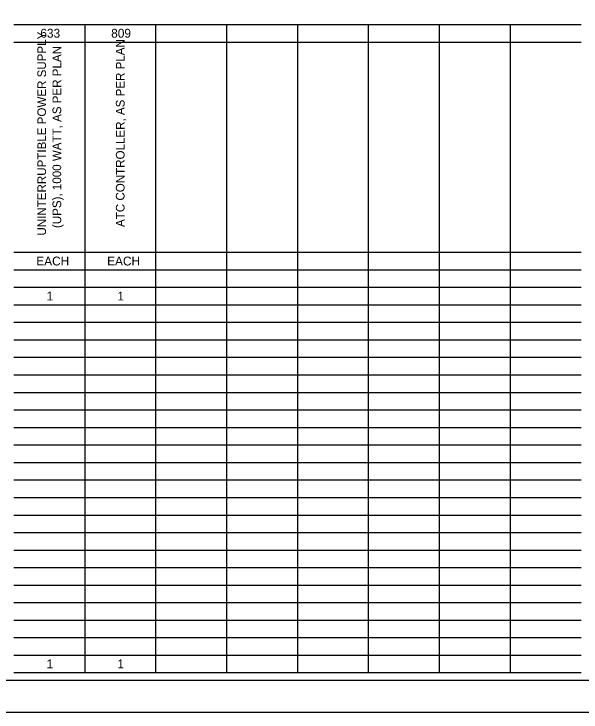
# Model space of a CAD drawing. Extents: x 0 to 34, y 0 to 22.
# Drawn here: x 16.33 to 25.28, y 0 to 11.03 of the extents above; entities that cross this region are included whole.
import ezdxf

# ---------------------------------------------------------------- set-up
doc = ezdxf.new("R2010")
doc.units = 0
for name, color, linetype in [('SH_Border', 7, 'Continuous'), ('SH_Cut_Line', 7, 'Continuous'), ('SH_Data', 7, 'Continuous')]:
    doc.layers.add(name, color=color, linetype=linetype)

msp = doc.modelspace()

# ---------------------------------------------------------------- linework, layer by layer
at = {"layer": 'SH_Border'}
msp.add_lwpolyline([(1.5, 21.5), (33.5, 21.5), (33.5, 0.5), (1.5, 0.5)], close=True, dxfattribs=at)
at = {"layer": 'SH_Cut_Line'}
msp.add_lwpolyline([(0, 0), (34, 0), (34, 22), (0, 22)], close=True, dxfattribs=at)
at = {"layer": 'SH_Data'}
for p, q in [((16.324, 10.86), (23.042, 10.86)), ((17.443, 10.86), (17.443, 10.583)), ((18.563, 10.86), (18.563, 10.583)), ((19.683, 10.86), (19.683, 10.583)), ((20.803, 10.86), (20.803, 10.583)), ((21.922, 10.86), (21.922, 10.583)), ((23.042, 10.86), (24.162, 10.86)), ((23.042, 10.86), (23.042, 10.583)), ((24.162, 10.86), (25.282, 10.86)), ((24.162, 10.86), (24.162, 10.583)), ((16.324, 10.583), (23.042, 10.583)), ((17.443, 10.583), (17.443, 10.307)), ((18.563, 10.583), (18.563, 10.307)), ((19.683, 10.583), (19.683, 10.307)), ((20.803, 10.583), (20.803, 10.307)), ((21.922, 10.583), (21.922, 10.307)), ((23.042, 10.583), (24.162, 10.583)), ((23.042, 10.583), (23.042, 10.307)), ((24.162, 10.583), (25.282, 10.583)), ((24.162, 10.583), (24.162, 10.307)), ((17.443, 10.307), (17.443, 10.03)), ((18.563, 10.307), (18.563, 10.03)), ((19.683, 10.307), (19.683, 10.03)), ((20.803, 10.307), (20.803, 10.03)), ((21.922, 10.307), (21.922, 10.03)), ((23.042, 10.307), (23.042, 10.03)), ((24.162, 10.307), (24.162, 10.03)), ((17.443, 10.03), (17.443, 9.753)), ((18.563, 10.03), (18.563, 9.753)), ((19.683, 10.03), (19.683, 9.753)), ((20.803, 10.03), (20.803, 9.753)), ((21.922, 10.03), (21.922, 9.753)), ((23.042, 10.03), (23.042, 9.753)), ((24.162, 10.03), (24.162, 9.753)), ((17.443, 9.753), (17.443, 9.476)), ((18.563, 9.753), (18.563, 9.476)), ((19.683, 9.753), (19.683, 9.476)), ((20.803, 9.753), (20.803, 9.476)), ((21.922, 9.753), (21.922, 9.476)), ((23.042, 9.753), (23.042, 9.476)), ((24.162, 9.753), (24.162, 9.476)), ((17.443, 9.476), (17.443, 9.2)), ((18.563, 9.476), (18.563, 9.2)), ((19.683, 9.476), (19.683, 9.2)), ((20.803, 9.476), (20.803, 9.2)), ((21.922, 9.476), (21.922, 9.2)), ((23.042, 9.476), (23.042, 9.2)), ((24.162, 9.476), (24.162, 9.2)), ((17.443, 9.2), (17.443, 8.923)), ((18.563, 9.2), (18.563, 8.923)), ((19.683, 9.2), (19.683, 8.923)), ((20.803, 9.2), (20.803, 8.923)), ((21.922, 9.2), (21.922, 8.923)), ((23.042, 9.2), (23.042, 8.923)), ((24.162, 9.2), (24.162, 8.923)), ((17.443, 8.923), (17.443, 8.646)), ((18.563, 8.923), (18.563, 8.646)), ((19.683, 8.923), (19.683, 8.646)), ((20.803, 8.923), (20.803, 8.646)), ((21.922, 8.923), (21.922, 8.646)), ((23.042, 8.923), (23.042, 8.646)), ((24.162, 8.923), (24.162, 8.646)), ((17.443, 8.646), (17.443, 8.37)), ((18.563, 8.646), (18.563, 8.37)), ((19.683, 8.646), (19.683, 8.37)), ((20.803, 8.646), (20.803, 8.37)), ((21.922, 8.646), (21.922, 8.37)), ((23.042, 8.646), (23.042, 8.37)), ((24.162, 8.646), (24.162, 8.37)), ((17.443, 8.37), (17.443, 8.093)), ((18.563, 8.37), (18.563, 8.093)), ((19.683, 8.37), (19.683, 8.093)), ((20.803, 8.37), (20.803, 8.093)), ((21.922, 8.37), (21.922, 8.093)), ((23.042, 8.37), (23.042, 8.093)), ((24.162, 8.37), (24.162, 8.093)), ((17.443, 8.093), (17.443, 7.816)), ((18.563, 8.093), (18.563, 7.816)), ((19.683, 8.093), (19.683, 7.816)), ((20.803, 8.093), (20.803, 7.816)), ((21.922, 8.093), (21.922, 7.816)), ((23.042, 8.093), (23.042, 7.816)), ((24.162, 8.093), (24.162, 7.816)), ((17.443, 7.816), (17.443, 7.54)), ((18.563, 7.816), (18.563, 7.54)), ((19.683, 7.816), (19.683, 7.54)), ((20.803, 7.816), (20.803, 7.54)), ((21.922, 7.816), (21.922, 7.54)), ((23.042, 7.816), (23.042, 7.54)), ((24.162, 7.816), (24.162, 7.54)), ((17.443, 7.54), (17.443, 7.263)), ((18.563, 7.54), (18.563, 7.263)), ((19.683, 7.54), (19.683, 7.263)), ((20.803, 7.54), (20.803, 7.263)), ((21.922, 7.54), (21.922, 7.263)), ((23.042, 7.54), (23.042, 7.263)), ((24.162, 7.54), (24.162, 7.263)), ((16.324, 7.263), (23.042, 7.263)), ((17.443, 7.263), (17.443, 6.986)), ((18.563, 7.263), (18.563, 6.986)), ((19.683, 7.263), (19.683, 6.986)), ((20.803, 7.263), (20.803, 6.986)), ((21.922, 7.263), (21.922, 6.986)), ((23.042, 7.263), (24.162, 7.263)), ((23.042, 7.263), (23.042, 6.986)), ((24.162, 7.263), (25.282, 7.263)), ((24.162, 7.263), (24.162, 6.986)), ((16.324, 6.986), (23.042, 6.986)), ((17.443, 6.986), (17.443, 6.709)), ((18.563, 6.986), (18.563, 6.709)), ((19.683, 6.986), (19.683, 6.709)), ((20.803, 6.986), (20.803, 6.709)), ((21.922, 6.986), (21.922, 6.709)), ((23.042, 6.986), (24.162, 6.986)), ((23.042, 6.986), (23.042, 6.709)), ((24.162, 6.986), (25.282, 6.986)), ((24.162, 6.986), (24.162, 6.709)), ((16.324, 6.709), (23.042, 6.709)), ((17.443, 6.709), (17.443, 6.433)), ((18.563, 6.709), (18.563, 6.433)), ((19.683, 6.709), (19.683, 6.433)), ((20.803, 6.709), (20.803, 6.433)), ((21.922, 6.709), (21.922, 6.433)), ((23.042, 6.709), (24.162, 6.709)), ((23.042, 6.709), (23.042, 6.433)), ((24.162, 6.709), (25.282, 6.709)), ((24.162, 6.709), (24.162, 6.433)), ((16.324, 6.433), (23.042, 6.433)), ((17.443, 6.433), (17.443, 5.879)), ((18.563, 6.433), (18.563, 5.879)), ((19.683, 6.433), (19.683, 5.879)), ((20.803, 6.433), (20.803, 5.879)), ((21.922, 6.433), (21.922, 5.879)), ((23.042, 6.433), (24.162, 6.433)), ((23.042, 6.433), (23.042, 5.879)), ((24.162, 6.433), (25.282, 6.433)), ((24.162, 6.433), (24.162, 5.879)), ((16.324, 6.156), (23.042, 6.156)), ((23.042, 6.156), (24.162, 6.156)), ((24.162, 6.156), (25.282, 6.156)), ((16.324, 5.879), (23.042, 5.879)), ((17.443, 5.879), (17.443, 5.603)), ((18.563, 5.879), (18.563, 5.603)), ((19.683, 5.879), (19.683, 5.603)), ((20.803, 5.879), (20.803, 5.603)), ((21.922, 5.879), (21.922, 5.603)), ((23.042, 5.879), (24.162, 5.879)), ((23.042, 5.879), (23.042, 5.603)), ((24.162, 5.879), (25.282, 5.879)), ((24.162, 5.879), (24.162, 5.603)), ((16.324, 5.603), (23.042, 5.603)), ((17.443, 5.603), (17.443, 5.326)), ((18.563, 5.603), (18.563, 5.326)), ((19.683, 5.603), (19.683, 5.326)), ((20.803, 5.603), (20.803, 5.326)), ((21.922, 5.603), (21.922, 5.326)), ((23.042, 5.603), (24.162, 5.603)), ((23.042, 5.603), (23.042, 5.326)), ((24.162, 5.603), (25.282, 5.603)), ((24.162, 5.603), (24.162, 5.326)), ((16.324, 5.326), (23.042, 5.326)), ((17.443, 5.326), (17.443, 5.049)), ((18.563, 5.326), (18.563, 5.049)), ((19.683, 5.326), (19.683, 5.049)), ((20.803, 5.326), (20.803, 5.049)), ((21.922, 5.326), (21.922, 5.049)), ((23.042, 5.326), (24.162, 5.326)), ((23.042, 5.326), (23.042, 5.049)), ((24.162, 5.326), (25.282, 5.326)), ((24.162, 5.326), (24.162, 5.049)), ((16.324, 5.049), (23.042, 5.049)), ((17.443, 5.049), (17.443, 4.496)), ((18.563, 5.049), (18.563, 4.496)), ((19.683, 5.049), (19.683, 4.496)), ((20.803, 5.049), (20.803, 4.496)), ((21.922, 5.049), (21.922, 4.496)), ((23.042, 5.049), (24.162, 5.049)), ((23.042, 5.049), (23.042, 4.496)), ((24.162, 5.049), (25.282, 5.049)), ((24.162, 5.049), (24.162, 4.496)), ((16.324, 4.772), (23.042, 4.772)), ((23.042, 4.772), (24.162, 4.772)), ((24.162, 4.772), (25.282, 4.772)), ((16.324, 4.496), (23.042, 4.496)), ((17.443, 4.496), (17.443, 4.219)), ((18.563, 4.496), (18.563, 4.219)), ((19.683, 4.496), (19.683, 4.219)), ((20.803, 4.496), (20.803, 4.219)), ((21.922, 4.496), (21.922, 4.219)), ((23.042, 4.496), (24.162, 4.496)), ((23.042, 4.496), (23.042, 4.219)), ((24.162, 4.496), (25.282, 4.496)), ((24.162, 4.496), (24.162, 4.219)), ((16.324, 4.219), (23.042, 4.219)), ((17.443, 4.219), (17.443, 3.942)), ((18.563, 4.219), (18.563, 3.942)), ((19.683, 4.219), (19.683, 3.942)), ((20.803, 4.219), (20.803, 3.942)), ((21.922, 4.219), (21.922, 3.942)), ((23.042, 4.219), (24.162, 4.219)), ((23.042, 4.219), (23.042, 3.942)), ((24.162, 4.219), (25.282, 4.219)), ((24.162, 4.219), (24.162, 3.942)), ((16.324, 3.942), (23.042, 3.942)), ((17.443, 3.942), (17.443, 3.666)), ((18.563, 3.942), (18.563, 3.666)), ((19.683, 3.942), (19.683, 3.666)), ((20.803, 3.942), (20.803, 3.666)), ((21.922, 3.942), (21.922, 3.666)), ((23.042, 3.942), (24.162, 3.942)), ((23.042, 3.942), (23.042, 3.666)), ((24.162, 3.942), (25.282, 3.942)), ((24.162, 3.942), (24.162, 3.666)), ((16.324, 3.666), (23.042, 3.666)), ((17.443, 3.666), (17.443, 3.112)), ((18.563, 3.666), (18.563, 3.112)), ((19.683, 3.666), (19.683, 3.112)), ((20.803, 3.666), (20.803, 3.112)), ((21.922, 3.666), (21.922, 3.112)), ((23.042, 3.666), (24.162, 3.666)), ((23.042, 3.666), (23.042, 3.112)), ((24.162, 3.666), (25.282, 3.666)), ((24.162, 3.666), (24.162, 3.112)), ((16.324, 3.389), (23.042, 3.389)), ((23.042, 3.389), (24.162, 3.389)), ((24.162, 3.389), (25.282, 3.389)), ((16.324, 3.112), (23.042, 3.112)), ((17.443, 3.112), (17.443, 2.836)), ((18.563, 3.112), (18.563, 2.836)), ((19.683, 3.112), (19.683, 2.836)), ((20.803, 3.112), (20.803, 2.836)), ((21.922, 3.112), (21.922, 2.836)), ((23.042, 3.112), (24.162, 3.112)), ((23.042, 3.112), (23.042, 2.836)), ((24.162, 3.112), (25.282, 3.112)), ((24.162, 3.112), (24.162, 2.836)), ((16.324, 2.836), (23.042, 2.836)), ((17.443, 2.836), (17.443, 2.005)), ((18.563, 2.836), (18.563, 2.005)), ((19.683, 2.836), (19.683, 2.005)), ((20.803, 2.836), (20.803, 2.005)), ((21.922, 2.836), (21.922, 2.005)), ((23.042, 2.836), (24.162, 2.836)), ((23.042, 2.836), (23.042, 2.005)), ((24.162, 2.836), (25.282, 2.836)), ((24.162, 2.836), (24.162, 2.005)), ((16.324, 2.559), (23.042, 2.559)), ((23.042, 2.559), (24.162, 2.559)), ((24.162, 2.559), (25.282, 2.559)), ((16.324, 2.282), (23.042, 2.282)), ((23.042, 2.282), (24.162, 2.282)), ((24.162, 2.282), (25.282, 2.282)), ((16.324, 2.005), (23.042, 2.005)), ((17.443, 2.005), (17.443, 1.729)), ((18.563, 2.005), (18.563, 1.729)), ((19.683, 2.005), (19.683, 1.729)), ((20.803, 2.005), (20.803, 1.729)), ((21.922, 2.005), (21.922, 1.729)), ((23.042, 2.005), (24.162, 2.005)), ((23.042, 2.005), (23.042, 1.729)), ((24.162, 2.005), (25.282, 2.005)), ((24.162, 2.005), (24.162, 1.729)), ((16.324, 1.729), (23.042, 1.729)), ((17.443, 1.729), (17.443, 1.452)), ((18.563, 1.729), (18.563, 1.452)), ((19.683, 1.729), (19.683, 1.452)), ((20.803, 1.729), (20.803, 1.452)), ((21.922, 1.729), (21.922, 1.452)), ((23.042, 1.729), (24.162, 1.729)), ((23.042, 1.729), (23.042, 1.452)), ((24.162, 1.729), (25.282, 1.729)), ((24.162, 1.729), (24.162, 1.452)), ((16.324, 1.452), (23.042, 1.452)), ((17.443, 1.452), (17.443, 1.175)), ((18.563, 1.452), (18.563, 1.175)), ((19.683, 1.452), (19.683, 1.175)), ((20.803, 1.452), (20.803, 1.175)), ((21.922, 1.452), (21.922, 1.175)), ((23.042, 1.452), (24.162, 1.452)), ((23.042, 1.452), (23.042, 1.175)), ((24.162, 1.452), (25.282, 1.452)), ((24.162, 1.452), (24.162, 1.175)), ((16.324, 1.175), (23.042, 1.175)), ((17.443, 1.175), (17.443, 0.899)), ((18.563, 1.175), (18.563, 0.899)), ((19.683, 1.175), (19.683, 0.899)), ((20.803, 1.175), (20.803, 0.899)), ((21.922, 1.175), (21.922, 0.899)), ((23.042, 1.175), (24.162, 1.175)), ((23.042, 1.175), (23.042, 0.899)), ((24.162, 1.175), (25.282, 1.175)), ((24.162, 1.175), (24.162, 0.899)), ((16.324, 0.899), (23.042, 0.899)), ((17.443, 0.899), (17.443, 0.622)), ((18.563, 0.899), (18.563, 0.622)), ((19.683, 0.899), (19.683, 0.622)), ((20.803, 0.899), (20.803, 0.622)), ((21.922, 0.899), (21.922, 0.622)), ((23.042, 0.899), (24.162, 0.899)), ((23.042, 0.899), (23.042, 0.622)), ((24.162, 0.899), (25.282, 0.899)), ((24.162, 0.899), (24.162, 0.622)), ((16.324, 0.622), (23.042, 0.622)), ((23.042, 0.622), (24.162, 0.622)), ((24.162, 0.622), (25.282, 0.622))]:
    msp.add_line(p, q, dxfattribs=at)

# ---------------------------------------------------------------- texts
for s, p in [('UNINTERRUPTIBLE POWER SUPPLY ', (16.832, 7.526)), ('ATC CONTROLLER, AS PER PLAN', (18.072, 7.662)), ('(UPS), 1000 WATT, AS PER PLAN', (17.071, 7.645))]:
    msp.add_text(s, height=0.13675, rotation=90, dxfattribs=at).set_placement(p)
for s, p in [('633', (16.742, 10.652)), ('809', (17.861, 10.652)), ('EACH', (16.678, 7.054)), ('EACH', (17.797, 7.054)), ('1', (16.84, 6.501)), ('1', (17.959, 6.501)), ('1', (16.84, 0.69)), ('1', (17.959, 0.69))]:
    msp.add_text(s, height=0.14, dxfattribs=at).set_placement(p)

doc.saveas('drawing.dxf')
